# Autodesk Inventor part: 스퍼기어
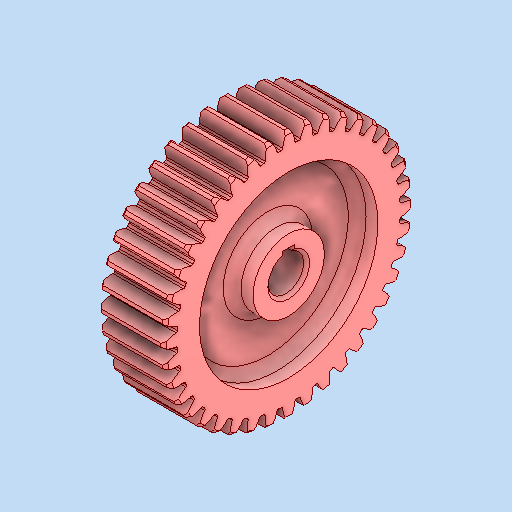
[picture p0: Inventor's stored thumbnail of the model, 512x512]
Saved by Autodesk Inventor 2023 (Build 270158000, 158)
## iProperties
Created: 2024-11
Part Number: 스퍼기어
Material: 강철, 탄소
Document SubType Name: Modeling
Designer: asung
Density: 7.85 g/cm^3
Appearance: 기본값
Author: jhkim
Sending System: Autodesk Inventor 2025
Preprocessor: ST-DEVELOPER v20
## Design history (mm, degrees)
node "스퍼기어1"
node "솔리드2"
node "솔리드1"
